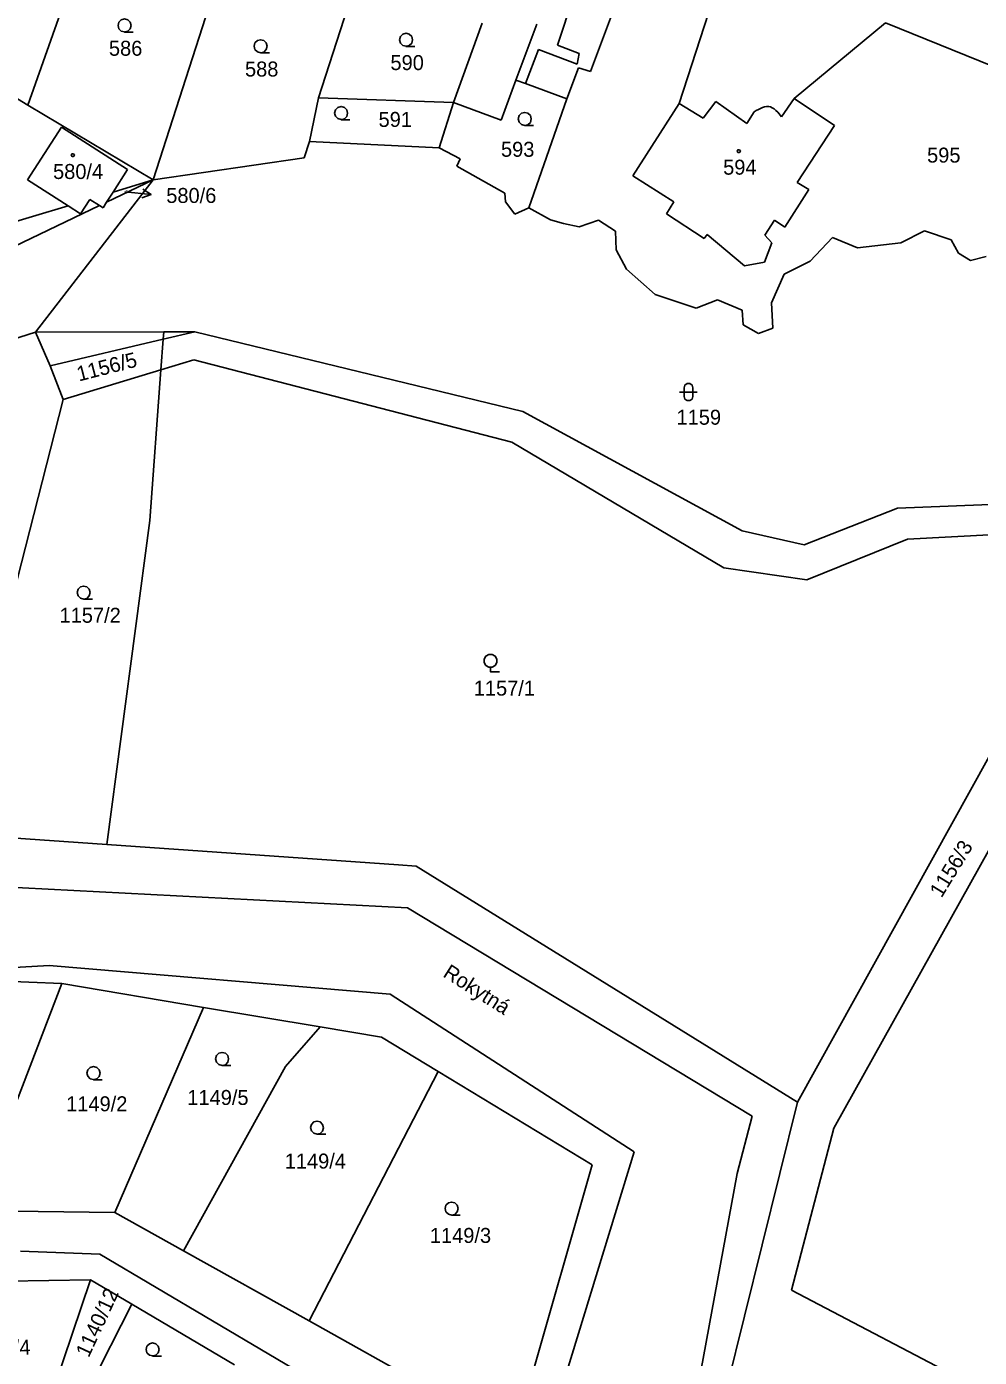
# Model space of a CAD drawing. Extents: x -621797 to -620972, y -1175539 to -1174697.
# Drawn here: x -621592 to -621483.9, y -1175130.5 to -1174979.5 of the extents above; entities that cross this region are included whole.
import ezdxf

# ---------------------------------------------------------------- set-up
doc = ezdxf.new("R2010")
doc.units = 0
for name, color, linetype in [('INZ mimo EON - nadz', 7, 'Continuous'), ('Rozvod plynu EON', 7, 'Continuous'), ('SDEL EON', 7, 'Continuous'), ('SDEL EON - popis', 7, 'Continuous'), ('Silnoproud EON', 7, 'Continuous'), ('Silnoproud EON - popis', 7, 'Continuous')]:
    doc.layers.add(name, color=color, linetype=linetype)

msp = doc.modelspace()

# ---------------------------------------------------------------- linework, layer by layer
at = {"layer": 'INZ mimo EON - nadz'}
msp.add_line((-621577.906, -1174998.543), (-621580.89, -1174998.23), dxfattribs=at)
msp.add_lwpolyline([(-621578.849, -1174997.941), (-621577.906, -1174998.543), (-621578.953, -1174998.936)], dxfattribs=at)
at = {"layer": 'Rozvod plynu EON'}
for points in [[(-621586.71, -1174993.92), (-621586.62, -1174994.07), (-621586.71, -1174994.22), (-621586.89, -1174994.22), (-621586.98, -1174994.07), (-621586.89, -1174993.92)], [(-621511.11, -1174993.48), (-621511.02, -1174993.63), (-621511.11, -1174993.78), (-621511.29, -1174993.78), (-621511.38, -1174993.63), (-621511.29, -1174993.48)]]:
    msp.add_lwpolyline(points, close=True, dxfattribs=at)
at = {"layer": 'SDEL EON'}
for points in [[(-621580.92, -1174980.1), (-621581.3, -1174980), (-621581.57, -1174979.73), (-621581.67, -1174979.36), (-621581.57, -1174978.99), (-621581.3, -1174978.72), (-621580.93, -1174978.62), (-621580.56, -1174978.72), (-621580.29, -1174978.99), (-621580.19, -1174979.37), (-621580.29, -1174979.75), (-621580.56, -1174980.02), (-621580.94, -1174980.12), (-621579.94, -1174980.12)], [(-621548.96, -1174981.73), (-621549.34, -1174981.63), (-621549.61, -1174981.36), (-621549.71, -1174980.99), (-621549.61, -1174980.62), (-621549.34, -1174980.35), (-621548.97, -1174980.25), (-621548.6, -1174980.35), (-621548.33, -1174980.62), (-621548.23, -1174981), (-621548.33, -1174981.38), (-621548.6, -1174981.65), (-621548.98, -1174981.75), (-621547.98, -1174981.75)], [(-621565.47, -1174982.46), (-621565.85, -1174982.36), (-621566.12, -1174982.09), (-621566.22, -1174981.72), (-621566.12, -1174981.35), (-621565.85, -1174981.08), (-621565.48, -1174980.98), (-621565.11, -1174981.08), (-621564.84, -1174981.35), (-621564.74, -1174981.73), (-621564.84, -1174982.11), (-621565.11, -1174982.38), (-621565.49, -1174982.48), (-621564.49, -1174982.48)], [(-621556.33, -1174990.04), (-621556.71, -1174989.94), (-621556.98, -1174989.67), (-621557.08, -1174989.3), (-621556.98, -1174988.93), (-621556.71, -1174988.66), (-621556.34, -1174988.56), (-621555.97, -1174988.66), (-621555.7, -1174988.93), (-621555.6, -1174989.31), (-621555.7, -1174989.69), (-621555.97, -1174989.96), (-621556.35, -1174990.06), (-621555.35, -1174990.06)], [(-621535.49, -1174990.71), (-621535.87, -1174990.61), (-621536.14, -1174990.34), (-621536.24, -1174989.97), (-621536.14, -1174989.6), (-621535.87, -1174989.33), (-621535.5, -1174989.23), (-621535.13, -1174989.33), (-621534.86, -1174989.6), (-621534.76, -1174989.98), (-621534.86, -1174990.36), (-621535.13, -1174990.63), (-621535.51, -1174990.73), (-621534.51, -1174990.73)], [(-621517.91, -1175020.98), (-621516.64, -1175020.98), (-621515.91, -1175020.98)], [(-621585.56, -1175044.47), (-621585.94, -1175044.37), (-621586.21, -1175044.1), (-621586.31, -1175043.73), (-621586.21, -1175043.36), (-621585.94, -1175043.09), (-621585.57, -1175042.99), (-621585.2, -1175043.09), (-621584.93, -1175043.36), (-621584.83, -1175043.74), (-621584.93, -1175044.12), (-621585.2, -1175044.39), (-621585.58, -1175044.49), (-621584.58, -1175044.49)], [(-621539.38, -1175052.2), (-621539.57, -1175052.2), (-621539.91, -1175052.01), (-621540.1, -1175051.67), (-621540.1, -1175051.28), (-621539.91, -1175050.94), (-621539.57, -1175050.75), (-621539.18, -1175050.75), (-621538.84, -1175050.94), (-621538.65, -1175051.28), (-621538.65, -1175051.67), (-621538.84, -1175052.01), (-621539.18, -1175052.2), (-621539.37, -1175052.2), (-621539.37, -1175052.73), (-621538.37, -1175052.73)], [(-621569.84, -1175097.4), (-621570.22, -1175097.3), (-621570.49, -1175097.03), (-621570.59, -1175096.66), (-621570.49, -1175096.29), (-621570.22, -1175096.02), (-621569.85, -1175095.92), (-621569.48, -1175096.02), (-621569.21, -1175096.29), (-621569.11, -1175096.67), (-621569.21, -1175097.05), (-621569.48, -1175097.32), (-621569.86, -1175097.42), (-621568.86, -1175097.42)], [(-621584.44, -1175099.01), (-621584.82, -1175098.91), (-621585.09, -1175098.64), (-621585.19, -1175098.27), (-621585.09, -1175097.9), (-621584.82, -1175097.63), (-621584.45, -1175097.53), (-621584.08, -1175097.63), (-621583.81, -1175097.9), (-621583.71, -1175098.28), (-621583.81, -1175098.66), (-621584.08, -1175098.93), (-621584.46, -1175099.03), (-621583.46, -1175099.03)], [(-621559.07, -1175105.2), (-621559.45, -1175105.1), (-621559.72, -1175104.83), (-621559.82, -1175104.46), (-621559.72, -1175104.09), (-621559.45, -1175103.82), (-621559.08, -1175103.72), (-621558.71, -1175103.82), (-621558.44, -1175104.09), (-621558.34, -1175104.47), (-621558.44, -1175104.85), (-621558.71, -1175105.12), (-621559.09, -1175105.22), (-621558.09, -1175105.22)], [(-621543.79, -1175114.39), (-621544.17, -1175114.29), (-621544.44, -1175114.02), (-621544.54, -1175113.65), (-621544.44, -1175113.28), (-621544.17, -1175113.01), (-621543.8, -1175112.91), (-621543.43, -1175113.01), (-621543.16, -1175113.28), (-621543.06, -1175113.66), (-621543.16, -1175114.04), (-621543.43, -1175114.31), (-621543.81, -1175114.41), (-621542.81, -1175114.41)], [(-621577.73, -1175130.38), (-621578.11, -1175130.28), (-621578.38, -1175130.01), (-621578.48, -1175129.64), (-621578.38, -1175129.27), (-621578.11, -1175129), (-621577.74, -1175128.9), (-621577.37, -1175129), (-621577.1, -1175129.27), (-621577, -1175129.65), (-621577.1, -1175130.03), (-621577.37, -1175130.3), (-621577.75, -1175130.4), (-621576.75, -1175130.4)]]:
    msp.add_lwpolyline(points, dxfattribs=at)
msp.add_lwpolyline([(-621517.41, -1175020.48), (-621517.31, -1175020.19), (-621517.06, -1175020.01), (-621516.75, -1175020.01), (-621516.5, -1175020.19), (-621516.4, -1175020.48), (-621516.4, -1175021.48), (-621516.5, -1175021.77), (-621516.75, -1175021.95), (-621517.06, -1175021.95), (-621517.31, -1175021.77), (-621517.41, -1175021.48)], close=True, dxfattribs=at)
at = {"layer": 'SDEL EON - popis'}
for p, q in [((-621531.79, -1174981.59), (-621529.78, -1174975.54)), ((-621534.14, -1174979.21), (-621536.49, -1174985.57)), ((-621535.41, -1174985.97), (-621533.95, -1174982.09)), ((-621533.95, -1174982.09), (-621529.53, -1174983.76)), ((-621529.3, -1174982.56), (-621531.79, -1174981.59)), ((-621529.53, -1174983.76), (-621529.3, -1174982.56)), ((-621515.23, -1174989.89), (-621517.97, -1174988.23)), ((-621513.79, -1174987.98), (-621515.23, -1174989.89)), ((-621510.28, -1174990.49), (-621513.79, -1174987.98)), ((-621504.91, -1174987.66), (-621506.34, -1174989.75)), ((-621509.45, -1174989.17), (-621510.28, -1174990.49)), ((-621506.34, -1174989.75), (-621506.78, -1174989.2)), ((-621576.54, -1175014.98), (-621589.38, -1175017.99)), ((-621572.94, -1175014.14), (-621576.54, -1175014.98)), ((-621595.84, -1175077.08), (-621548.79, -1175079.5)), ((-621548.79, -1175079.5), (-621509.68, -1175103.16)), ((-621589.49, -1175086.06), (-621629.74, -1175088.46)), ((-621550.77, -1175089.31), (-621589.49, -1175086.06)), ((-621523.08, -1175107.22), (-621550.77, -1175089.31)), ((-621509.68, -1175103.16), (-621511.39, -1175109.68)), ((-621530.82, -1175132.54), (-621523.08, -1175107.22)), ((-621511.39, -1175109.68), (-621516.07, -1175135.19))]:
    msp.add_line(p, q, dxfattribs=at)
msp.add_spline([(-621506.78, -1174989.2), (-621507.61, -1174988.6), (-621509.45, -1174989.17)], degree=3, dxfattribs=at)
at = {"layer": 'Silnoproud EON'}
for p, q in [((-621583.68, -1174965.08), (-621591.92, -1174988.4)), ((-621521.85, -1174967.99), (-621528.03, -1174984.58)), ((-621570.25, -1174973.87), (-621577.67, -1174996.89)), ((-621554.62, -1174974.24), (-621558.9, -1174987.56)), ((-621517.97, -1174988.23), (-621514.14, -1174976.41)), ((-621540.33, -1174979.1), (-621543.58, -1174988.09)), ((-621494.53, -1174979.08), (-621504.91, -1174987.66)), ((-621494.53, -1174979.08), (-621480.81, -1174984.62)), ((-621605.91, -1174979.93), (-621591.92, -1174988.4)), ((-621529.39, -1174984.17), (-621530.71, -1174987.69)), ((-621528.03, -1174984.58), (-621529.39, -1174984.17)), ((-621536.49, -1174985.57), (-621538.17, -1174990.11)), ((-621535.41, -1174985.97), (-621536.49, -1174985.57)), ((-621530.71, -1174987.69), (-621535.41, -1174985.97)), ((-621591.92, -1174988.4), (-621577.67, -1174996.89)), ((-621558.9, -1174987.56), (-621559.92, -1174992.54)), ((-621543.58, -1174988.09), (-621558.9, -1174987.56)), ((-621543.58, -1174988.09), (-621545.23, -1174993.24)), ((-621538.17, -1174990.11), (-621543.58, -1174988.09)), ((-621530.71, -1174987.69), (-621535.04, -1175000.07)), ((-621523.21, -1174996.42), (-621517.97, -1174988.23)), ((-621504.91, -1174987.66), (-621500.35, -1174990.72)), ((-621588.08, -1174990.89), (-621591.94, -1174996.89)), ((-621588.08, -1174990.89), (-621580.59, -1174995.7)), ((-621500.35, -1174990.72), (-621504.58, -1174997.19)), ((-621559.92, -1174992.54), (-621560.52, -1174994.37)), ((-621545.23, -1174993.24), (-621559.92, -1174992.54)), ((-621560.52, -1174994.37), (-621577.67, -1174996.89)), ((-621542.81, -1174994.51), (-621545.23, -1174993.24)), ((-621580.59, -1174995.7), (-621582.23, -1174998.27)), ((-621543.2, -1174995.35), (-621542.81, -1174994.51)), ((-621537.76, -1174998.39), (-621543.2, -1174995.35)), ((-621591.94, -1174996.89), (-621587.34, -1174999.82)), ((-621591.02, -1175014.17), (-621577.67, -1174996.89)), ((-621577.67, -1174996.89), (-621582.96, -1174999.41)), ((-621582.23, -1174998.27), (-621577.67, -1174996.89)), ((-621518.57, -1174999.38), (-621523.21, -1174996.42)), ((-621504.58, -1174997.19), (-621503.24, -1174997.98)), ((-621582.23, -1174998.27), (-621582.96, -1174999.41)), ((-621537.7, -1174999.38), (-621537.76, -1174998.39)), ((-621503.24, -1174997.98), (-621505.98, -1175002.26)), ((-621601.69, -1175004.16), (-621587.34, -1174999.82)), ((-621583.76, -1174999.8), (-621599.34, -1175007.24)), ((-621587.34, -1174999.82), (-621585.91, -1175000.73)), ((-621585.91, -1175000.73), (-621584.87, -1174999.1)), ((-621584.87, -1174999.1), (-621583.76, -1174999.8)), ((-621583.36, -1175000.05), (-621583.76, -1174999.8)), ((-621582.96, -1174999.41), (-621583.36, -1175000.05)), ((-621536.61, -1175000.77), (-621537.7, -1174999.38)), ((-621535.04, -1175000.07), (-621536.61, -1175000.77)), ((-621532.59, -1175001.43), (-621535.04, -1175000.07)), ((-621519.39, -1175000.75), (-621518.57, -1174999.38)), ((-621531.1, -1175001.86), (-621532.59, -1175001.43)), ((-621529.31, -1175002.21), (-621531.1, -1175001.86)), ((-621527.13, -1175001.47), (-621529.31, -1175002.21)), ((-621525.2, -1175002.73), (-621527.13, -1175001.47)), ((-621515.11, -1175003.54), (-621519.39, -1175000.75)), ((-621507.15, -1175001.47), (-621508.24, -1175003.17)), ((-621505.98, -1175002.26), (-621507.15, -1175001.47)), ((-621525.12, -1175004.83), (-621525.2, -1175002.73)), ((-621514.78, -1175003.09), (-621515.11, -1175003.54)), ((-621510.56, -1175006.64), (-621514.78, -1175003.09)), ((-621508.24, -1175003.17), (-621507.44, -1175004.04)), ((-621500.57, -1175003.43), (-621503.09, -1175006.1)), ((-621497.73, -1175004.59), (-621500.57, -1175003.43)), ((-621490.11, -1175002.69), (-621492.79, -1175004.05)), ((-621487.08, -1175003.68), (-621490.11, -1175002.69)), ((-621523.95, -1175007.02), (-621525.12, -1175004.83)), ((-621507.44, -1175004.04), (-621508.27, -1175006.24)), ((-621492.79, -1175004.05), (-621497.73, -1175004.59)), ((-621486.25, -1175005.2), (-621487.08, -1175003.68)), ((-621508.27, -1175006.24), (-621510.56, -1175006.64)), ((-621503.09, -1175006.1), (-621506.03, -1175007.61)), ((-621484.9, -1175006.03), (-621486.25, -1175005.2)), ((-621483.1, -1175005.58), (-621484.9, -1175006.03)), ((-621520.7, -1175009.91), (-621523.95, -1175007.02)), ((-621506.03, -1175007.61), (-621507.47, -1175010.86)), ((-621516.04, -1175011.45), (-621520.7, -1175009.91)), ((-621513.6, -1175010.49), (-621516.04, -1175011.45)), ((-621510.83, -1175011.66), (-621513.6, -1175010.49)), ((-621507.47, -1175010.86), (-621507.32, -1175013.73)), ((-621510.7, -1175013.34), (-621510.83, -1175011.66)), ((-621508.97, -1175014.32), (-621510.7, -1175013.34)), ((-621507.32, -1175013.73), (-621508.97, -1175014.32)), ((-621591.02, -1175014.17), (-621628.52, -1175025.94)), ((-621576.48, -1175014.15), (-621591.02, -1175014.17)), ((-621591.02, -1175014.17), (-621589.38, -1175017.99)), ((-621576.8, -1175018.44), (-621576.54, -1175014.98)), ((-621576.54, -1175014.98), (-621576.48, -1175014.15)), ((-621572.94, -1175014.14), (-621576.48, -1175014.15)), ((-621535.7, -1175023.17), (-621572.94, -1175014.14)), ((-621589.38, -1175017.99), (-621587.9, -1175021.83)), ((-621576.8, -1175018.44), (-621587.9, -1175021.83)), ((-621578.06, -1175035.55), (-621576.8, -1175018.44)), ((-621573.06, -1175017.3), (-621576.8, -1175018.44)), ((-621536.97, -1175026.68), (-621573.06, -1175017.3)), ((-621587.9, -1175021.83), (-621593.12, -1175042.28)), ((-621510.8, -1175036.74), (-621535.7, -1175023.17)), ((-621512.9, -1175040.94), (-621536.97, -1175026.68)), ((-621480.74, -1175033.65), (-621493.2, -1175034.17)), ((-621493.2, -1175034.17), (-621503.78, -1175038.33)), ((-621582.93, -1175072.34), (-621578.06, -1175035.55)), ((-621503.78, -1175038.33), (-621510.8, -1175036.74)), ((-621492.03, -1175037.67), (-621503.49, -1175042.29)), ((-621482.07, -1175037.14), (-621492.03, -1175037.67)), ((-621503.49, -1175042.29), (-621512.9, -1175040.94)), ((-621504.52, -1175101.59), (-621471.46, -1175041.86)), ((-621500.4, -1175104.54), (-621466.98, -1175044.53)), ((-621582.93, -1175072.34), (-621600.03, -1175071.15)), ((-621549.81, -1175074.63), (-621582.93, -1175072.34)), ((-621547.84, -1175074.77), (-621549.81, -1175074.63)), ((-621504.52, -1175101.59), (-621547.84, -1175074.77)), ((-621606.5, -1175087.4), (-621591.78, -1175087.96)), ((-621588.05, -1175088.1), (-621597.97, -1175113.92)), ((-621591.78, -1175087.96), (-621588.05, -1175088.1)), ((-621588.05, -1175088.1), (-621571.96, -1175090.81)), ((-621571.96, -1175090.81), (-621582.03, -1175114.1)), ((-621571.96, -1175090.81), (-621558.72, -1175093.04)), ((-621558.72, -1175093.04), (-621562.64, -1175097.53)), ((-621558.72, -1175093.04), (-621551.76, -1175094.21)), ((-621551.76, -1175094.21), (-621545.33, -1175098.1)), ((-621574.24, -1175118.44), (-621562.64, -1175097.53)), ((-621559.97, -1175126.4), (-621545.33, -1175098.1)), ((-621545.33, -1175098.1), (-621527.86, -1175108.67)), ((-621512.68, -1175134.5), (-621504.52, -1175101.59)), ((-621505.23, -1175122.91), (-621500.4, -1175104.54)), ((-621527.86, -1175108.67), (-621536.65, -1175139.4)), ((-621597.97, -1175113.92), (-621590.72, -1175114)), ((-621590.72, -1175114), (-621582.03, -1175114.1)), ((-621574.24, -1175118.44), (-621582.03, -1175114.1)), ((-621592.73, -1175118.48), (-621583.73, -1175118.84)), ((-621583.73, -1175118.84), (-621484.26, -1175177.55)), ((-621559.97, -1175126.4), (-621574.24, -1175118.44)), ((-621594.26, -1175121.88), (-621584.8, -1175121.74)), ((-621584.8, -1175121.74), (-621589.84, -1175136.61)), ((-621584.8, -1175121.74), (-621580.09, -1175124.51)), ((-621480.19, -1175136), (-621505.23, -1175122.91)), ((-621586.88, -1175137.77), (-621580.09, -1175124.51)), ((-621580.09, -1175124.51), (-621568.43, -1175131.39)), ((-621536.65, -1175139.4), (-621559.97, -1175126.4))]:
    msp.add_line(p, q, dxfattribs=at)

# ---------------------------------------------------------------- texts
at = {"layer": 'INZ mimo EON - nadz'}
for s, p in [('580/6', (-621576.193, -1174999.51)), ('1159', (-621518.267, -1175024.68))]:
    msp.add_text(s, height=1.7, dxfattribs=at).set_placement(p)
msp.add_text('Rokytná', height=1.7, rotation=327.61727, dxfattribs=at).set_placement((-621544.889, -1175087.261))
at = {"layer": 'Silnoproud EON - popis'}
for s, height, p in [('586', 1.7, (-621582.703, -1174982.8)), ('588', 1.7, (-621567.253, -1174985.16)), ('590', 1.7, (-621550.743, -1174984.43)), ('591', 1.7, (-621552.093, -1174990.88)), ('593', 1.7, (-621538.193, -1174994.27)), ('595', 1.7, (-621489.823, -1174994.93)), ('580/4', 1.7, (-621589.043, -1174996.79)), ('594', 1.7, (-621512.973, -1174996.3)), ('580/6', 0.1, (-621580.836, -1174998.16)), ('1157/2', 1.7, (-621588.307, -1175047.16)), ('1157/1', 1.7, (-621541.287, -1175055.43)), ('1149/5', 1.7, (-621573.803, -1175101.89)), ('1149/2', 1.7, (-621587.557, -1175102.61)), ('1149/4', 1.7, (-621562.746, -1175109.11)), ('1149/3', 1.7, (-621546.267, -1175117.55))]:
    msp.add_text(s, height=height, dxfattribs=at).set_placement(p)
for s, rotation, p in [('1156/5', 14.38124, (-621586.11, -1175019.782)), ('1156/3', 58.49899, (-621488.185, -1175078.465)), ('1140/12', 65.03071, (-621585.002, -1175130.655)), ('1140/4', 2.6929, (-621598.508, -1175130.532))]:
    msp.add_text(s, height=1.7, rotation=rotation, dxfattribs=at).set_placement(p)

doc.saveas('drawing.dxf')
